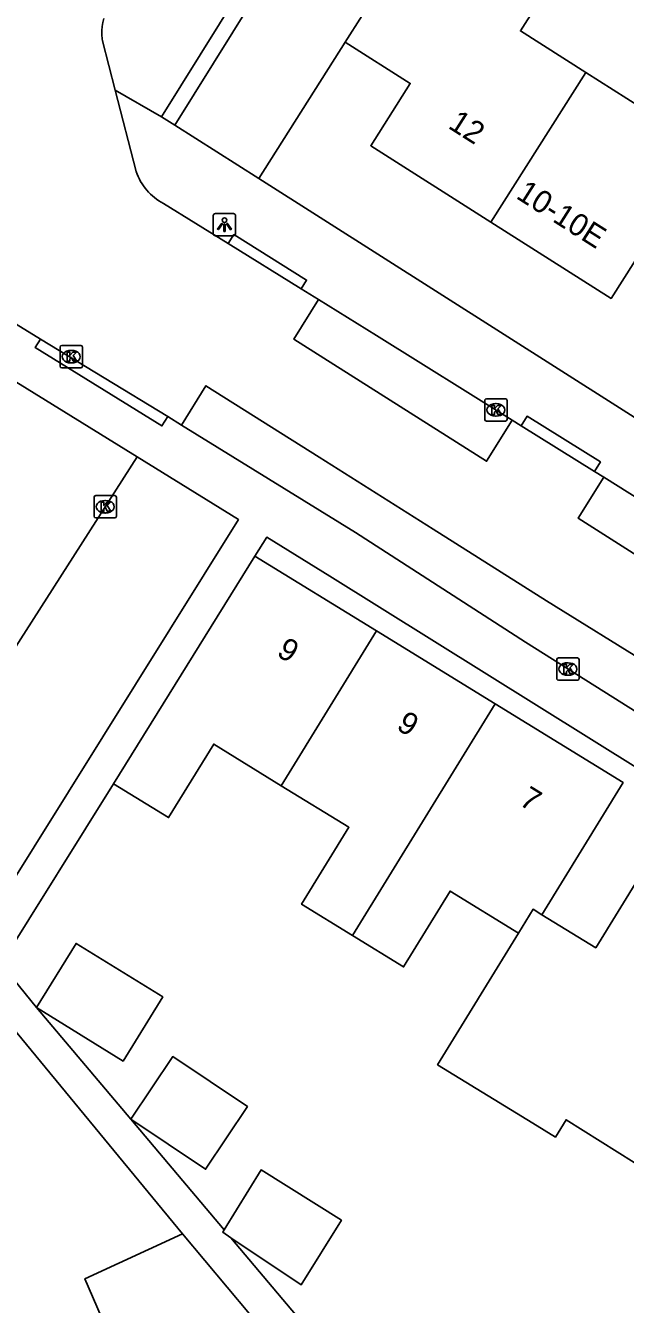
# Model space of a CAD drawing. Extents: x 160861 to 161308, y 384024 to 384878.
# Drawn here: x 161137.9 to 161164.7, y 384365.1 to 384422.3 of the extents above; entities that cross this region are included whole.
import ezdxf

# ---------------------------------------------------------------- set-up
doc = ezdxf.new("R2010")
doc.units = 0
for name, color, linetype in [('IMGEO_Groenvoorziening', 7, 'Continuous'), ('IMGEO_Kolk', 7, 'Continuous'), ('IMGEO_Lichtpunt', 7, 'Continuous'), ('IMGEO_Pand', 7, 'Continuous'), ('IMGEO_Pand_nummerreeks', 7, 'Continuous'), ('IMGEO_Rijbaan_lokaal_open', 7, 'Continuous'), ('IMGEO_Voetpad_open', 7, 'Continuous')]:
    doc.layers.add(name, color=color, linetype=linetype)

msp = doc.modelspace()

# ---------------------------------------------------------------- linework, layer by layer
at = {"layer": 'IMGEO_Groenvoorziening'}
for points in [[(161158.438, 384439.993), (161144.615, 384417.804)], [(161148.364, 384415.421), (161152.235, 384421.518)]]:
    msp.add_lwpolyline(points, dxfattribs=at)
at = {"layer": 'IMGEO_Kolk'}
for p, q in [((161139.489, 384407.042), (161139.489, 384407.894)), ((161139.564, 384407.968), (161140.416, 384407.968)), ((161139.977, 384407.748), (161140.002, 384407.748)), ((161140.49, 384407.894), (161140.49, 384407.042)), ((161140.416, 384406.968), (161139.564, 384406.968)), ((161140, 384407.188), (161139.975, 384407.188)), ((161158.461, 384404.662), (161158.461, 384405.514)), ((161158.536, 384405.588), (161159.388, 384405.588)), ((161158.949, 384405.368), (161158.974, 384405.368)), ((161159.462, 384405.514), (161159.462, 384404.662)), ((161159.388, 384404.588), (161158.536, 384404.588)), ((161158.972, 384404.808), (161158.947, 384404.808)), ((161141.008, 384400.336), (161141.008, 384401.188)), ((161141.083, 384401.262), (161141.935, 384401.262)), ((161142.009, 384401.188), (161142.009, 384400.336)), ((161141.496, 384401.042), (161141.521, 384401.042)), ((161141.935, 384400.262), (161141.083, 384400.262)), ((161141.519, 384400.482), (161141.494, 384400.482)), ((161161.68, 384393.084), (161161.68, 384393.936)), ((161161.755, 384394.01), (161162.607, 384394.01)), ((161162.168, 384393.79), (161162.193, 384393.79)), ((161162.681, 384393.936), (161162.681, 384393.084)), ((161162.191, 384393.23), (161162.166, 384393.23)), ((161162.607, 384393.01), (161161.755, 384393.01))]:
    msp.add_line(p, q, dxfattribs=at)
for points in [[(161139.489, 384407.042), (161139.489, 384407.894)], [(161139.564, 384407.968), (161140.416, 384407.968)], [(161139.81, 384407.668), (161139.933, 384407.668), (161139.933, 384407.517), (161140.063, 384407.668), (161140.227, 384407.668), (161140.081, 384407.517), (161140.234, 384407.268), (161140.082, 384407.268), (161139.997, 384407.432), (161139.933, 384407.365), (161139.933, 384407.268), (161139.81, 384407.268), (161139.81, 384407.668)], [(161140.49, 384407.894), (161140.49, 384407.042)], [(161140.416, 384406.968), (161139.564, 384406.968)], [(161158.461, 384404.662), (161158.461, 384405.514)], [(161158.536, 384405.588), (161159.388, 384405.588)], [(161158.782, 384405.288), (161158.905, 384405.288), (161158.905, 384405.137), (161159.035, 384405.288), (161159.199, 384405.288), (161159.053, 384405.137), (161159.206, 384404.888), (161159.054, 384404.888), (161158.969, 384405.052), (161158.905, 384404.985), (161158.905, 384404.888), (161158.782, 384404.888), (161158.782, 384405.288)], [(161159.462, 384405.514), (161159.462, 384404.662)], [(161159.388, 384404.588), (161158.536, 384404.588)], [(161141.008, 384400.336), (161141.008, 384401.188)], [(161141.083, 384401.262), (161141.935, 384401.262)], [(161142.009, 384401.188), (161142.009, 384400.336)], [(161141.329, 384400.962), (161141.452, 384400.962), (161141.452, 384400.811), (161141.582, 384400.962), (161141.746, 384400.962), (161141.6, 384400.811), (161141.753, 384400.562), (161141.601, 384400.562), (161141.516, 384400.726), (161141.452, 384400.659), (161141.452, 384400.562), (161141.329, 384400.562), (161141.329, 384400.962)], [(161141.935, 384400.262), (161141.083, 384400.262)], [(161161.68, 384393.084), (161161.68, 384393.936)], [(161161.755, 384394.01), (161162.607, 384394.01)], [(161162.001, 384393.71), (161162.124, 384393.71), (161162.124, 384393.559), (161162.254, 384393.71), (161162.418, 384393.71), (161162.272, 384393.559), (161162.425, 384393.31), (161162.273, 384393.31), (161162.188, 384393.474), (161162.124, 384393.407), (161162.124, 384393.31), (161162.001, 384393.31), (161162.001, 384393.71)], [(161162.681, 384393.936), (161162.681, 384393.084)], [(161162.607, 384393.01), (161161.755, 384393.01)]]:
    msp.add_lwpolyline(points, dxfattribs=at)
for centre, start, end in [((161139.566, 384407.892), 91.552, 178.448), ((161139.566, 384407.892), 91.552, 178.448), ((161140.414, 384407.892), 1.552, 88.448), ((161140.414, 384407.892), 1.552, 88.448), ((161139.566, 384407.044), 181.552, 268.448), ((161139.566, 384407.044), 181.552, 268.448), ((161140.414, 384407.044), 271.552, 358.448), ((161140.414, 384407.044), 271.552, 358.448), ((161158.538, 384405.512), 91.552, 178.448), ((161158.538, 384405.512), 91.552, 178.448), ((161159.386, 384405.512), 1.552, 88.448), ((161159.386, 384405.512), 1.552, 88.448), ((161158.538, 384404.664), 181.552, 268.448), ((161158.538, 384404.664), 181.552, 268.448), ((161159.386, 384404.664), 271.552, 358.448), ((161159.386, 384404.664), 271.552, 358.448), ((161141.085, 384401.186), 91.552, 178.448), ((161141.085, 384401.186), 91.552, 178.448), ((161141.933, 384401.186), 1.552, 88.448), ((161141.933, 384401.186), 1.552, 88.448), ((161141.085, 384400.338), 181.552, 268.448), ((161141.085, 384400.338), 181.552, 268.448), ((161141.933, 384400.338), 271.552, 358.448), ((161141.933, 384400.338), 271.552, 358.448), ((161161.757, 384393.934), 91.552, 178.448), ((161161.757, 384393.934), 91.552, 178.448), ((161162.605, 384393.934), 1.552, 88.448), ((161162.605, 384393.934), 1.552, 88.448), ((161161.757, 384393.086), 181.552, 268.448), ((161161.757, 384393.086), 181.552, 268.448), ((161162.605, 384393.086), 271.552, 358.448), ((161162.605, 384393.086), 271.552, 358.448)]:
    msp.add_arc(centre, 0.0765, start, end, dxfattribs=at)
for centre, major_axis, ratio, start_param, end_param in [((161139.976, 384407.468), (-0.387, 0.002), 0.722429, 4.712389, 7.853982), ((161140.001, 384407.468), (-0.39, 0.002), 0.717154, 1.570796, 4.712389), ((161158.948, 384405.088), (-0.387, 0.002), 0.722429, 4.712389, 7.853982), ((161158.973, 384405.088), (-0.39, 0.002), 0.717154, 1.570796, 4.712389), ((161141.495, 384400.762), (-0.387, 0.002), 0.722429, 4.712389, 7.853982), ((161141.52, 384400.762), (-0.39, 0.002), 0.717154, 1.570796, 4.712389), ((161162.167, 384393.51), (-0.387, 0.002), 0.722429, 4.712389, 7.853982), ((161162.192, 384393.51), (-0.39, 0.002), 0.717154, 1.570796, 4.712389)]:
    msp.add_ellipse(centre, major_axis=major_axis, ratio=ratio, start_param=start_param, end_param=end_param, dxfattribs=at)
at = {"layer": 'IMGEO_Lichtpunt'}
for p, q in [((161146.337, 384413.768), (161146.337, 384412.961)), ((161146.337, 384413.768), (161146.337, 384412.961)), ((161147.239, 384413.863), (161146.431, 384413.863)), ((161147.239, 384413.863), (161146.431, 384413.863)), ((161147.333, 384412.961), (161147.333, 384413.768)), ((161147.333, 384412.961), (161147.333, 384413.768)), ((161146.431, 384412.867), (161147.239, 384412.867)), ((161146.431, 384412.867), (161147.239, 384412.867))]:
    msp.add_line(p, q, dxfattribs=at)
for points in [[(161146.711, 384413.432), (161146.75, 384413.404), (161146.562, 384413.142), (161146.524, 384413.169), (161146.711, 384413.432)], [(161146.813, 384413.384), (161146.86, 384413.384), (161146.86, 384413.062), (161146.813, 384413.062), (161146.813, 384413.384)], [(161146.923, 384413.404), (161146.961, 384413.431), (161147.148, 384413.169), (161147.109, 384413.141), (161146.923, 384413.404)]]:
    msp.add_lwpolyline(points, dxfattribs=at)
msp.add_circle((161146.836, 384413.566), 0.0994, dxfattribs=at)
for centre, start, end in [((161146.431, 384413.768), 90, 180), ((161146.431, 384413.768), 90, 180), ((161147.239, 384413.768), 0, 90), ((161147.239, 384413.768), 0, 90), ((161146.431, 384412.961), 180, 270), ((161146.431, 384412.961), 180, 270), ((161147.239, 384412.961), 270, 0), ((161147.239, 384412.961), 270, 360)]:
    msp.add_arc(centre, 0.0946, start, end, dxfattribs=at)
at = {"layer": 'IMGEO_Pand'}
for points in [[(161152.235, 384421.518), (161156.787, 384428.682)], [(161156.787, 384428.682), (161161.007, 384426), (161162.133, 384425.285), (161160.058, 384422.019), (161162.986, 384420.159)], [(161152.235, 384421.518), (161155.136, 384419.675), (161153.368, 384416.891), (161158.74, 384413.478)], [(161162.986, 384420.159), (161166.037, 384418.22), (161168.098, 384421.463), (161173.083, 384418.296), (161173.348, 384418.127), (161169.779, 384412.511)], [(161158.74, 384413.478), (161162.986, 384420.159)], [(161169.346, 384412.403), (161166.673, 384414.102), (161164.109, 384410.066), (161158.74, 384413.478)], [(161141.873, 384388.387), (161148.197, 384398.55)], [(161153.626, 384395.214), (161148.197, 384398.55)], [(161149.375, 384388.298), (161153.626, 384395.214)], [(161158.923, 384391.959), (161153.626, 384395.214)], [(161152.558, 384381.603), (161158.923, 384391.959)], [(161161.016, 384382.534), (161164.647, 384388.441), (161158.923, 384391.959)], [(161149.375, 384388.298), (161146.354, 384390.155), (161144.337, 384386.873), (161141.873, 384388.387)], [(161152.558, 384381.603), (161150.282, 384383.002), (161152.396, 384386.442), (161149.375, 384388.298)], [(161170.985, 384380.821), (161165.417, 384384.3), (161163.423, 384381.055), (161161.016, 384382.534)], [(161159.968, 384381.713), (161156.917, 384383.588), (161154.836, 384380.203), (161152.558, 384381.603)], [(161161.016, 384382.534), (161160.622, 384382.776), (161159.968, 384381.713)], [(161166.879, 384374.249), (161165.143, 384371.47), (161162.099, 384373.371), (161161.623, 384372.596), (161160.615, 384373.216), (161156.355, 384375.834), (161159.968, 384381.713)], [(161138.437, 384378.386), (161140.208, 384381.252), (161144.079, 384378.86), (161142.308, 384375.994), (161138.437, 384378.386)], [(161142.654, 384373.398), (161144.528, 384376.195), (161147.864, 384373.96), (161145.99, 384371.163), (161142.654, 384373.398)], [(161147.12, 384368.101), (161150.256, 384365.995), (161152.064, 384368.884), (161148.473, 384371.131), (161146.826, 384368.45)], [(161148.95, 384363.508), (161142.882, 384361.001), (161140.6, 384366.267), (161144.963, 384368.273)], [(161144.963, 384368.273), (161148.95, 384363.508)], [(161146.826, 384368.45), (161146.76, 384368.343), (161147.12, 384368.101)]]:
    msp.add_lwpolyline(points, dxfattribs=at)
at = {"layer": 'IMGEO_Rijbaan_lokaal_open'}
for points in [[(161141.451, 384422.575), (161141.402, 384422.398), (161141.369, 384422.218), (161141.351, 384422.036), (161141.351, 384421.852), (161141.366, 384421.67), (161141.38, 384421.579), (161141.959, 384419.372)], [(161142.89, 384415.737), (161141.959, 384419.372)], [(161147.003, 384412.517), (161144.11, 384414.307)], [(161130.592, 384412.947), (161133.214, 384411.576), (161138.618, 384408.252)], [(161150.261, 384410.5), (161147.003, 384412.517)], [(161151.036, 384410.02), (161150.261, 384410.5)], [(161159.692, 384404.631), (161158.545, 384402.793), (161149.931, 384408.251), (161151.036, 384410.02)], [(161138.618, 384408.252), (161144.301, 384404.797)], [(161137.515, 384406.349), (161142.934, 384402.992)], [(161144.922, 384404.413), (161146.008, 384406.167), (161151.062, 384402.975), (161156.159, 384399.755), (161161.225, 384396.555), (161165.885, 384393.676), (161171.532, 384390.289), (161176.598, 384387.111), (161181.233, 384384.124), (161185.977, 384381.245), (161190.122, 384378.571), (161195.927, 384375.949)], [(161144.301, 384404.797), (161144.922, 384404.413)], [(161160.091, 384404.382), (161159.692, 384404.631)], [(161163.368, 384402.338), (161160.091, 384404.382)], [(161142.934, 384402.992), (161132.079, 384386.033)], [(161163.782, 384402.08), (161163.368, 384402.338)], [(161186.195, 384387.99), (161185.129, 384386.27), (161180.896, 384388.81), (161176.173, 384391.728), (161171.616, 384394.663), (161166.893, 384397.546), (161162.639, 384400.248), (161163.782, 384402.08)]]:
    msp.add_lwpolyline(points, dxfattribs=at)
msp.add_arc((161145.342, 384416.593), 2.597, 199.25, 241.6881, dxfattribs=at)
at = {"layer": 'IMGEO_Voetpad_open'}
for points in [[(161144.024, 384418.179), (161157.844, 384440.363)], [(161141.959, 384419.372), (161144.024, 384418.179)], [(161144.615, 384417.804), (161144.024, 384418.179)], [(161148.364, 384415.421), (161144.615, 384417.804)], [(161186.074, 384391.45), (161148.364, 384415.421)], [(161147.003, 384412.517), (161147.261, 384412.924), (161150.507, 384410.888), (161150.261, 384410.5)], [(161151.036, 384410.02), (161153.626, 384408.416), (161159.692, 384404.631)], [(161144.301, 384404.797), (161144.038, 384404.372), (161138.384, 384407.874), (161138.618, 384408.252)], [(161160.091, 384404.382), (161160.355, 384404.806), (161163.632, 384402.762), (161163.368, 384402.338)], [(161166.079, 384391.067), (161160.279, 384394.704), (161152.687, 384399.604), (161144.922, 384404.413)], [(161142.934, 384402.992), (161147.458, 384400.188), (161136.779, 384383.115), (161132.079, 384386.033)], [(161163.782, 384402.08), (161166.751, 384400.227), (161186.195, 384387.99)], [(161148.197, 384398.55), (161148.727, 384399.401), (161151.548, 384397.653), (161188.834, 384374.379)], [(161141.873, 384388.387), (161136.861, 384380.343)], [(161136.861, 384380.343), (161138.437, 384378.386)], [(161144.963, 384368.273), (161136.648, 384378.337)], [(161138.437, 384378.386), (161142.654, 384373.398)], [(161142.654, 384373.398), (161146.826, 384368.45)], [(161147.12, 384368.101), (161160.505, 384352.226)]]:
    msp.add_lwpolyline(points, dxfattribs=at)

# ---------------------------------------------------------------- texts
at = {"layer": 'IMGEO_Pand_nummerreeks'}
for s, rotation, p in [('12', 327.5675, (161156.782, 384417.707)), ('10-10E', 327.5649, (161159.817, 384414.572)), ('9', 328.4281, (161149.118, 384394.133)), ('9', 328.4281, (161154.47, 384390.845)), ('7', 328.4281, (161159.953, 384387.475))]:
    msp.add_text(s, height=1, rotation=rotation, dxfattribs=at).set_placement(p)

doc.saveas('drawing.dxf')
